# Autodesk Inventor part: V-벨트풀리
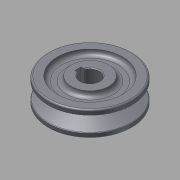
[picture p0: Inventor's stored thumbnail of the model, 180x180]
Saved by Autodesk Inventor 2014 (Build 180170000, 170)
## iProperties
Created: 2015-12
Part Number: V-벨트풀리
Material: 강철, 연강
Document SubType Name: Modeling
Designer: mdu
Density: 7.86 g/cm^3
Appearance: Steel
CustomPartVersion: 1
Author: mdu
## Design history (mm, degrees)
sketch "주 스케치"
  geometry: L1 (0, 16)-(27, 16); L2 (27, 16)-(27, 12.861); L3 (27, 12.861)-(16, 9.498); L4 (16, 9.498)-(16, 6.502); L5 (16, 6.502)-(27, 3.139); L6 (27, 3.139)-(27, 0); L7 (27, 0)-(0, 0); L8 (25, 12.25)-(25, 3.75); L9 (16, 8)-(25, 8); L10 (27, 12.861)-(27, 3.139); L11 (0, -3)-(0, 18) reference; L12 (0, 0)-(0, 16)
  constraints: 22 end point, 5 perpendicular, 2 collinear, 2 midpoint, 2 point on line, 1 parallel
  dimensions: "d0" = 8.5 distance of L8.start L8.end (= da_Bw); "d1" = 34 deg angle of L3 L5 (= da_Alfa); "d2" = 2 distance between parallel lines of L2 L8 (= da_c); "d6" = 16 distance between parallel lines of L7 L1 (computed from d5, da_ng, da_Sg); "d21" = 50 diameter of L8 L11 (= da_Dw); "d25" = 11 distance between parallel lines of L4 L10 (= da_Hd); "d27" = 8 distance between parallel lines of L7 L9 (= da_Se)
node "벨트 평면"
revolve "본체" stored, may be unused: angle "d7" = 90 deg
revolve "그루브" stored, may be unused: angle "d15" = 90 deg
feature "허브 키홈"
fillet "모깎기3" dims "d28" = 0.5, "d29" = 1, "d30" = 1
sketch "스케치2"
  geometry: C1 r 12 at (0, 0); C2 r 21 at (0, 0); 1 further point
  constraints: 2 centre point, 2 coincident
  dimensions: "d31" = 24 diameter of C1; "d32" = 42 diameter of C2
extrude "돌출1" cut sketch "스케치2" distance "d33" = 3; taper "d34" = 0 deg
fillet "모깎기4" dims "d35" = 3
node "작업 평면2"
chamfer "모따기1" distance "d36" = 0.5; stored, may be unused: second distance "d37" = 2, angle "d38" = 45 deg
body "Solid1"
pattern_linear "그루브 패턴" dims "d18" = 12 (= da_Sg)
mirror "대칭1"
other parameters: "d5" = 8 (= da_Se), "da_Bw" = 8.5 [user parameter; used in 1 equation term], "da_Alfa" = 34 deg [user parameter; used in 1 equation term], "da_c" = 2 [user parameter; used in 1 equation term], "da_Dw" = 50 [user parameter; used in 1 equation term], "da_Hd" = 11 [user parameter; used in 1 equation term], "da_Se" = 8 [user parameter; used in 2 equation terms], "da_Sg" = 12 [user parameter; used in 2 equation terms], "da_r1" = 0 [user parameter], "da_r2" = 0 [user parameter], "d24" = 0, "d26" = 0
